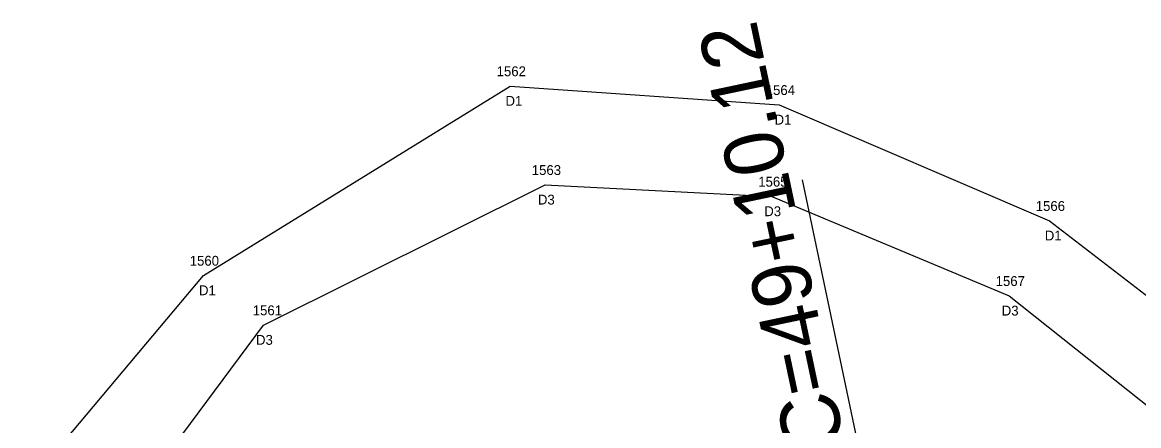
# Model space of a CAD drawing. Extents: x 1964982 to 1970452, y 1116335 to 1119906.
# Drawn here: x 1966585.2 to 1966698.6, y 1117493.9 to 1117534.8 of the extents above; entities that cross this region are included whole.
import ezdxf

# ---------------------------------------------------------------- set-up
doc = ezdxf.new("R2010")
doc.units = 0
for name, color, linetype in [('RD_EX_Driveway', 7, 'Continuous'), ('RD_EX_Driveway_txCode', 7, 'Continuous'), ('RD_HC_Data', 7, 'Continuous'), ('RD_SMD_Locator', 7, 'Continuous')]:
    doc.layers.add(name, color=color, linetype=linetype)

msp = doc.modelspace()

# ---------------------------------------------------------------- linework, layer by layer
at = {"layer": 'RD_EX_Driveway'}
for points in [[(1966578.03, 1117435.24), (1966571.58, 1117480.75), (1966567.97, 1117515.31), (1966576.56, 1117516.6), (1966582.11, 1117483.55), (1966603.62, 1117509.1), (1966634.75, 1117528.34), (1966662.08, 1117526.43), (1966689.52, 1117514.66), (1966711.52, 1117497.72), (1966730.01, 1117478.51), (1966744.03, 1117462.69), (1966734.11, 1117458.19)], [(1966589.3, 1117436.33), (1966587.98, 1117456.65), (1966594.08, 1117483.04), (1966609.7, 1117504.07), (1966638.32, 1117518.31), (1966661.32, 1117517.13), (1966685.43, 1117507.04), (1966705.56, 1117491.04), (1966722.87, 1117472.12), (1966734.11, 1117458.19)]]:
    msp.add_lwpolyline(points, dxfattribs=at)
at = {"layer": 'RD_HC_Data'}
msp.add_line((1966684.87, 1117421.95), (1966664.45, 1117518.83), dxfattribs=at)
at = {"layer": 'RD_SMD_Locator'}
for centre in [(1966634.75, 1117528.34), (1966634.75, 1117528.34), (1966662.08, 1117526.43), (1966662.08, 1117526.43), (1966638.32, 1117518.31), (1966638.32, 1117518.31), (1966661.32, 1117517.13), (1966661.32, 1117517.13), (1966689.52, 1117514.66), (1966689.52, 1117514.66), (1966603.62, 1117509.1), (1966603.62, 1117509.1), (1966685.43, 1117507.04), (1966685.43, 1117507.04), (1966609.7, 1117504.07), (1966609.7, 1117504.07)]:
    msp.add_circle(centre, 0.001, dxfattribs=at)

# ---------------------------------------------------------------- texts
at = {"layer": 'RD_EX_Driveway_txCode'}
for s, p in [('1562', (1966633.38, 1117529.34)), ('1562', (1966633.38, 1117529.34)), ('1564', (1966660.71, 1117527.43)), ('1564', (1966660.71, 1117527.43)), ('D1', (1966634.28, 1117526.34)), ('D1', (1966634.28, 1117526.34)), ('D1', (1966661.61, 1117524.43)), ('D1', (1966661.61, 1117524.43)), ('1563', (1966636.95, 1117519.31)), ('1563', (1966636.95, 1117519.31)), ('1565', (1966659.95, 1117518.13)), ('1565', (1966659.95, 1117518.13)), ('D3', (1966637.57, 1117516.31)), ('D3', (1966637.57, 1117516.31)), ('1566', (1966688.13, 1117515.66)), ('1566', (1966688.13, 1117515.66)), ('D3', (1966660.56, 1117515.13)), ('D3', (1966660.56, 1117515.13)), ('D1', (1966689.05, 1117512.66)), ('D1', (1966689.05, 1117512.66)), ('1560', (1966602.21, 1117510.1)), ('1560', (1966602.21, 1117510.1)), ('1567', (1966684.06, 1117508.04)), ('1567', (1966684.06, 1117508.04)), ('D1', (1966603.15, 1117507.1)), ('D1', (1966603.15, 1117507.1)), ('1561', (1966608.61, 1117505.07)), ('1561', (1966608.61, 1117505.07)), ('D3', (1966684.68, 1117505.04)), ('D3', (1966684.68, 1117505.04)), ('D3', (1966608.94, 1117502.07)), ('D3', (1966608.94, 1117502.07))]:
    msp.add_text(s, height=1, dxfattribs=at).set_placement(p)
at = {"layer": 'RD_HC_Data'}
msp.add_text('PC=49+10.12', height=6, rotation=101.9047, dxfattribs=at).set_placement((1966669.91, 1117486.75))

doc.saveas('drawing.dxf')
